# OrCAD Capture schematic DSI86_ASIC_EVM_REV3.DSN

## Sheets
1 PAGE05 AMBIENT LIGHT: size A; title: AMBIENT LIGHT SENSOR; rev: A.0; company: Texas Instruments, CIS/ICP; note: DSI86_ASIC_EVM_REV1
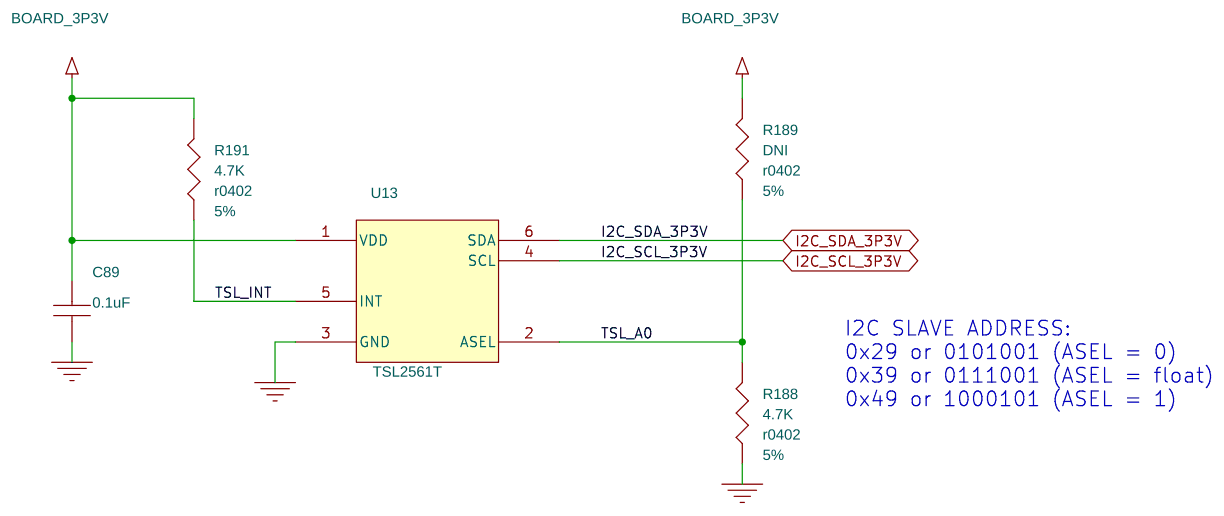
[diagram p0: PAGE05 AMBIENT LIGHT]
2 PAGE01 Title Page: title: SN65DSI86/96 EVM BLOCK DIAGRAM
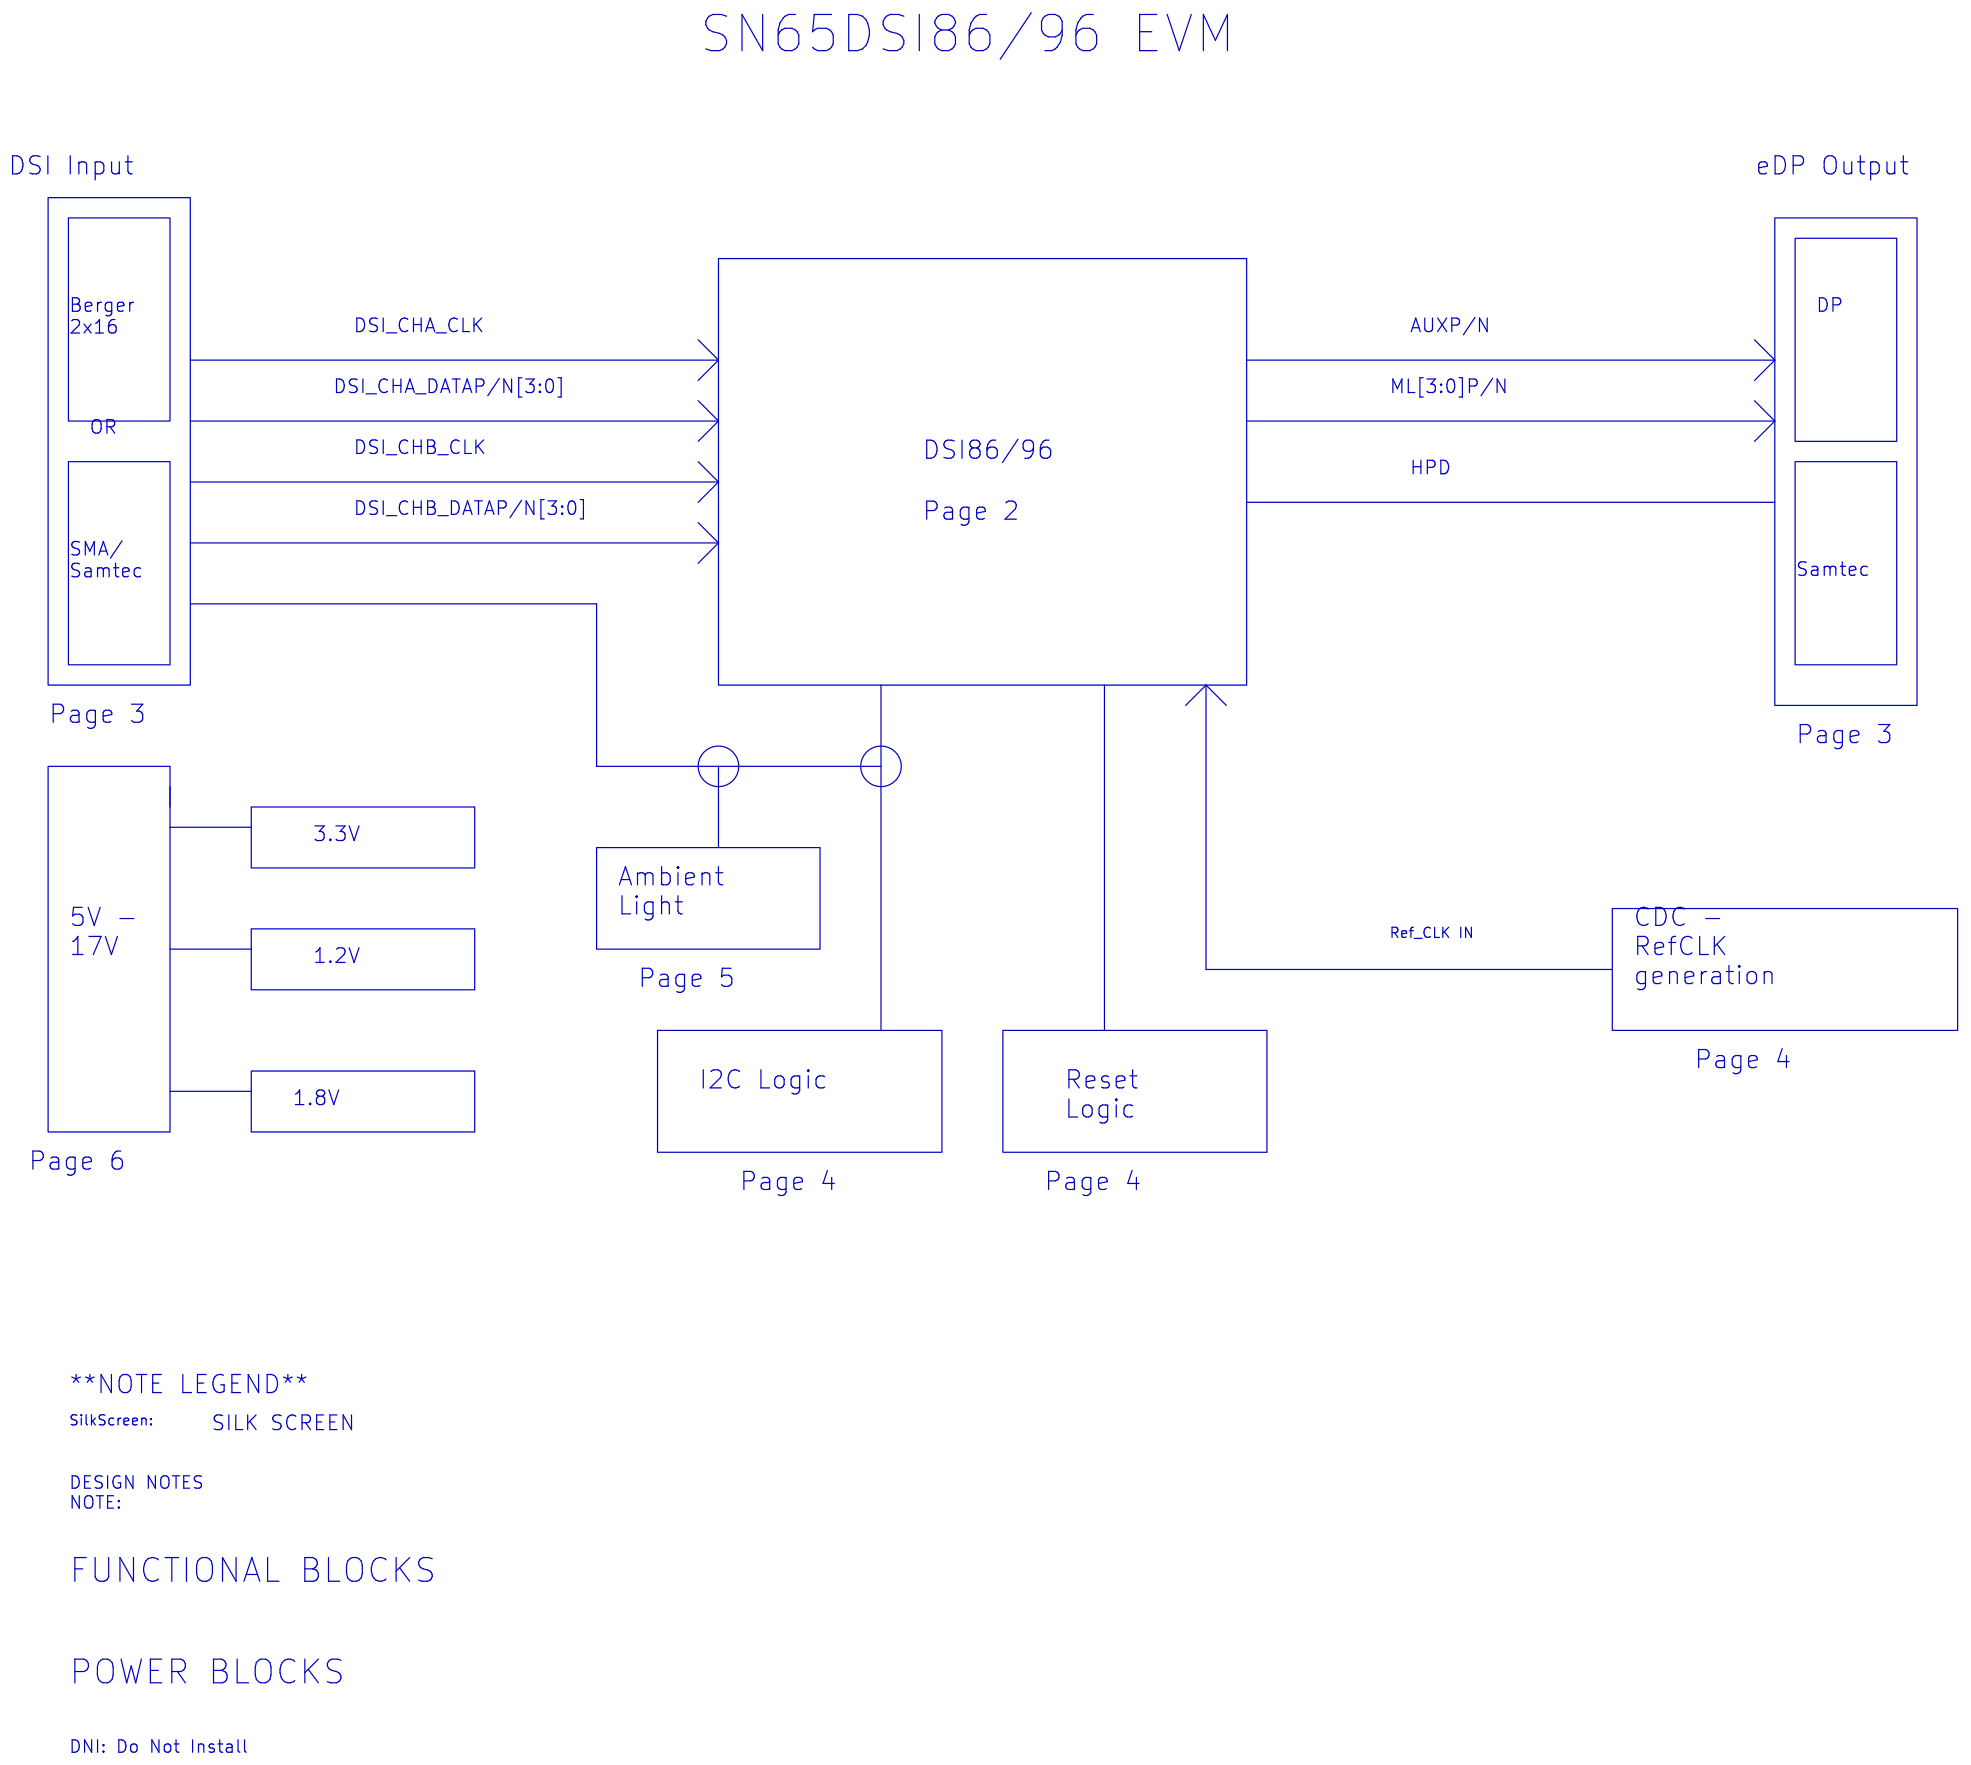
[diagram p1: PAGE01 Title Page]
3 PAGE02 DSI86: size C; title: SN65DSI86/96
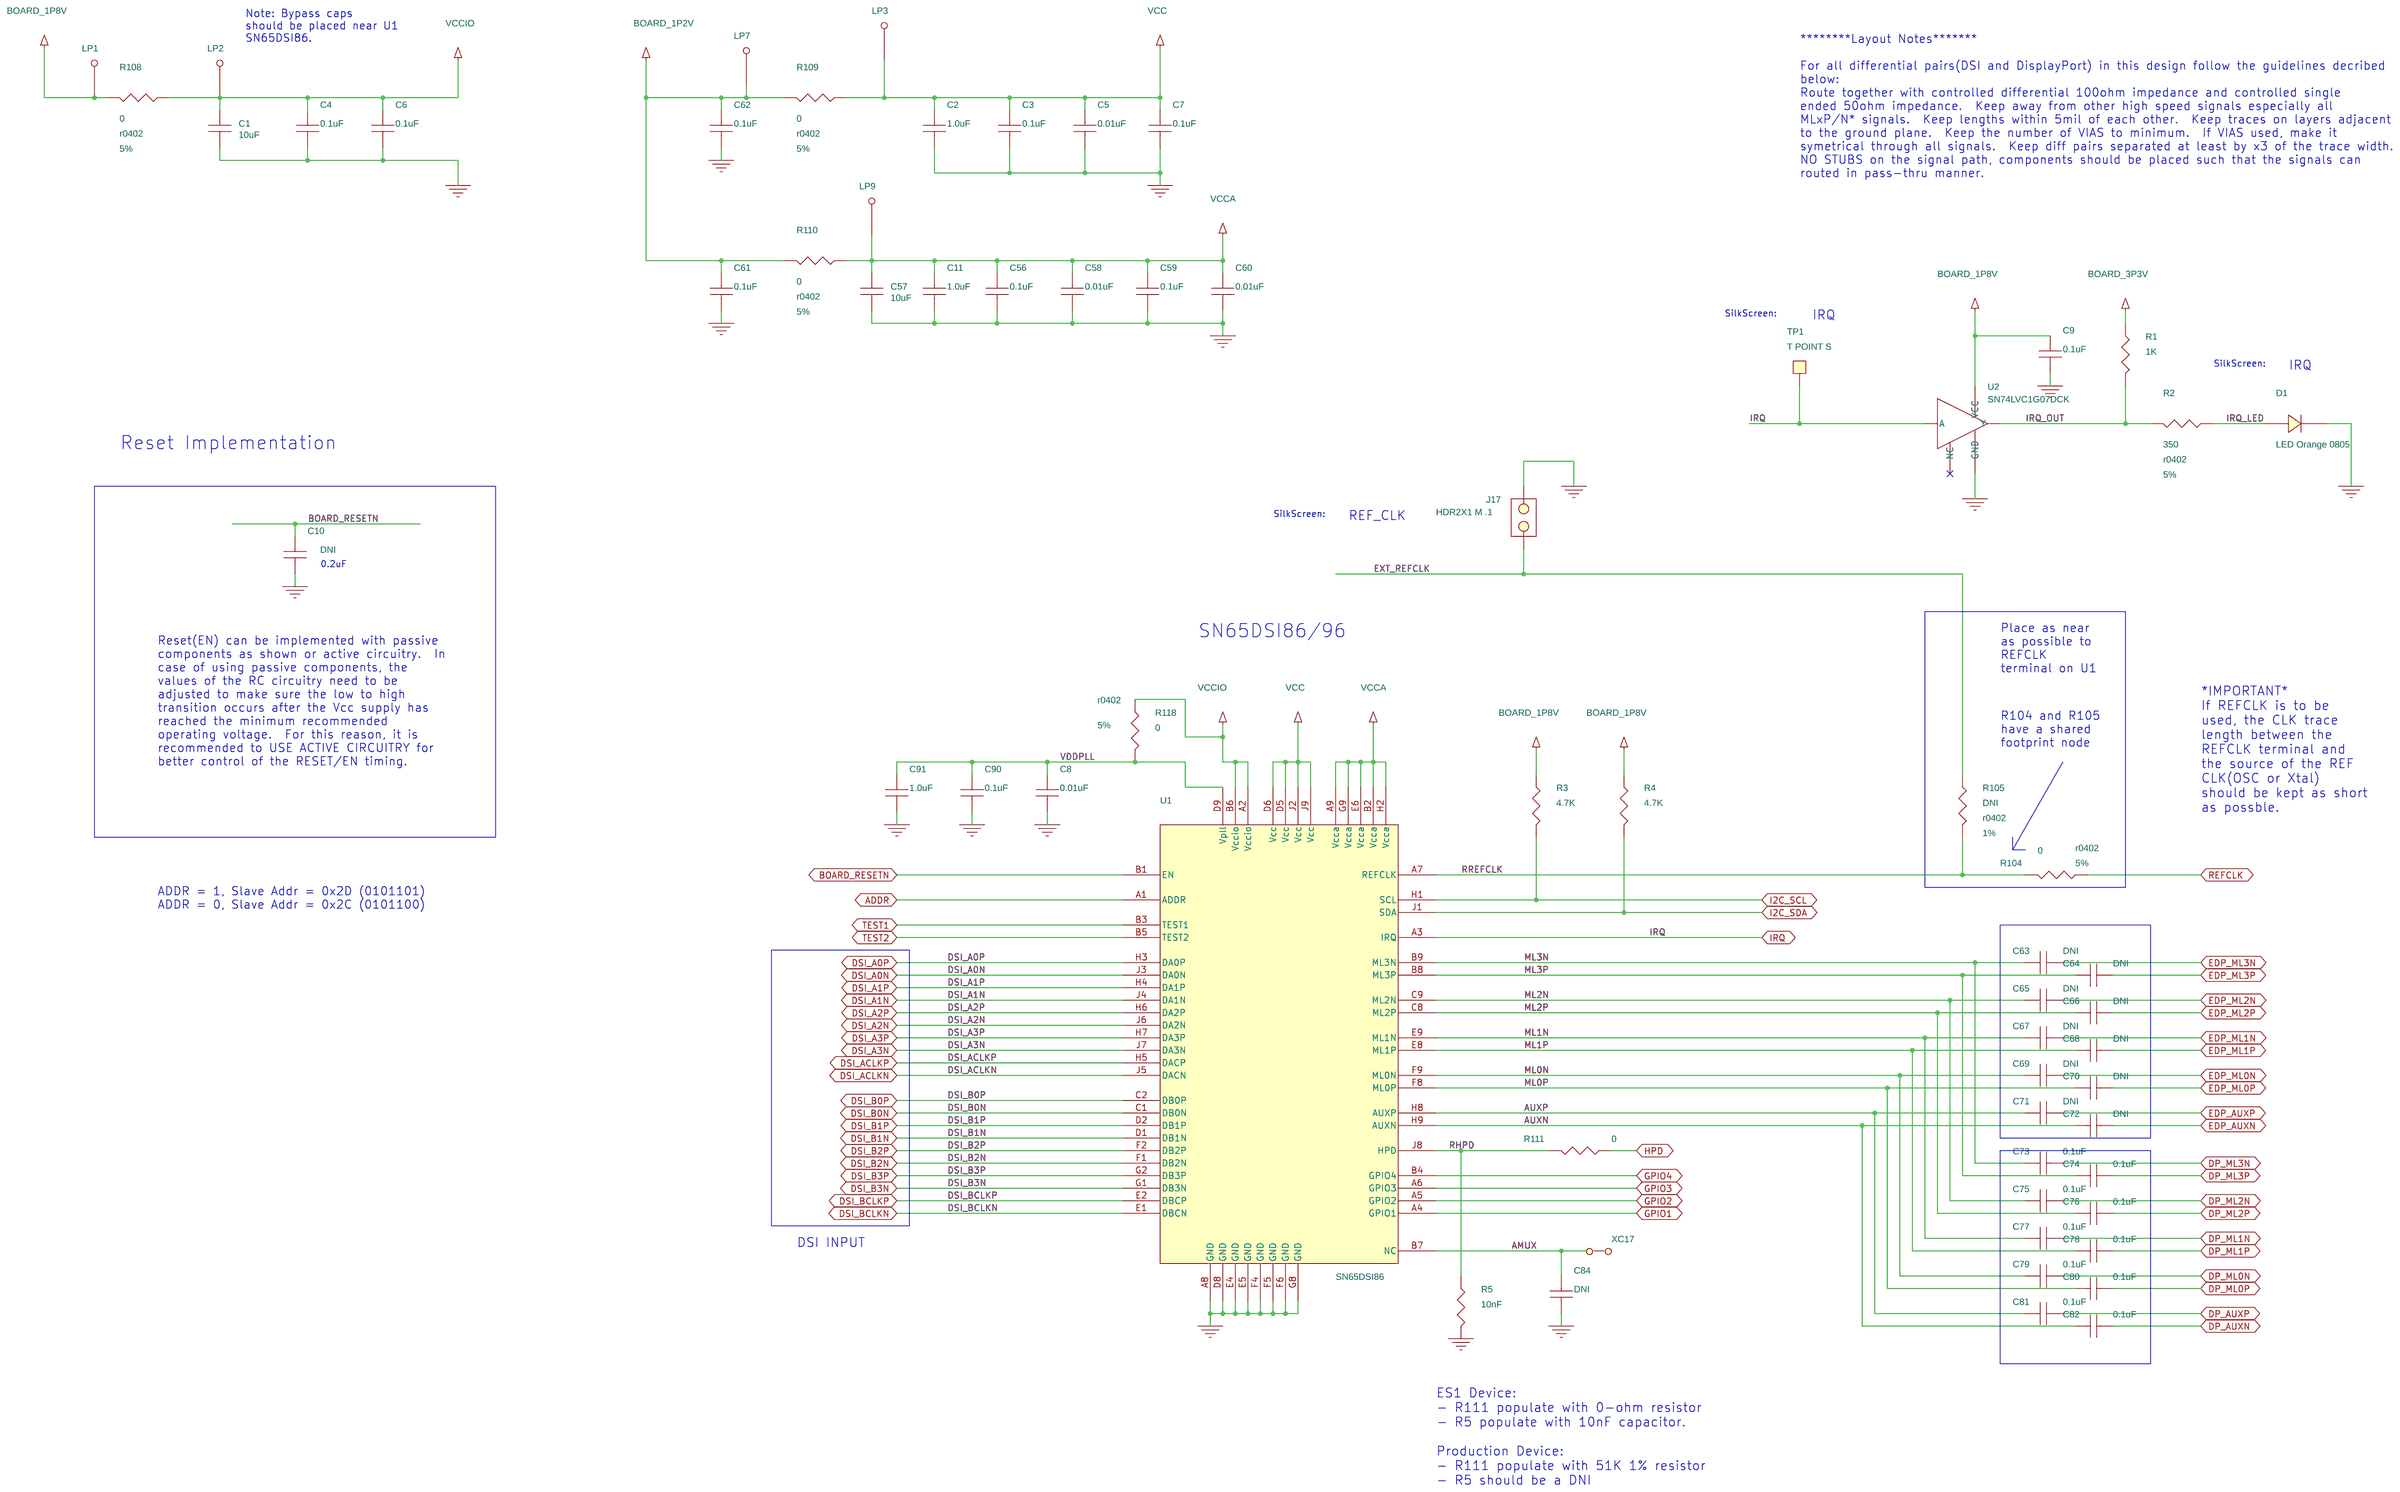
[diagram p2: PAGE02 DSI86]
4 PAGE03 Connectors: size D; title: CONNECTORS
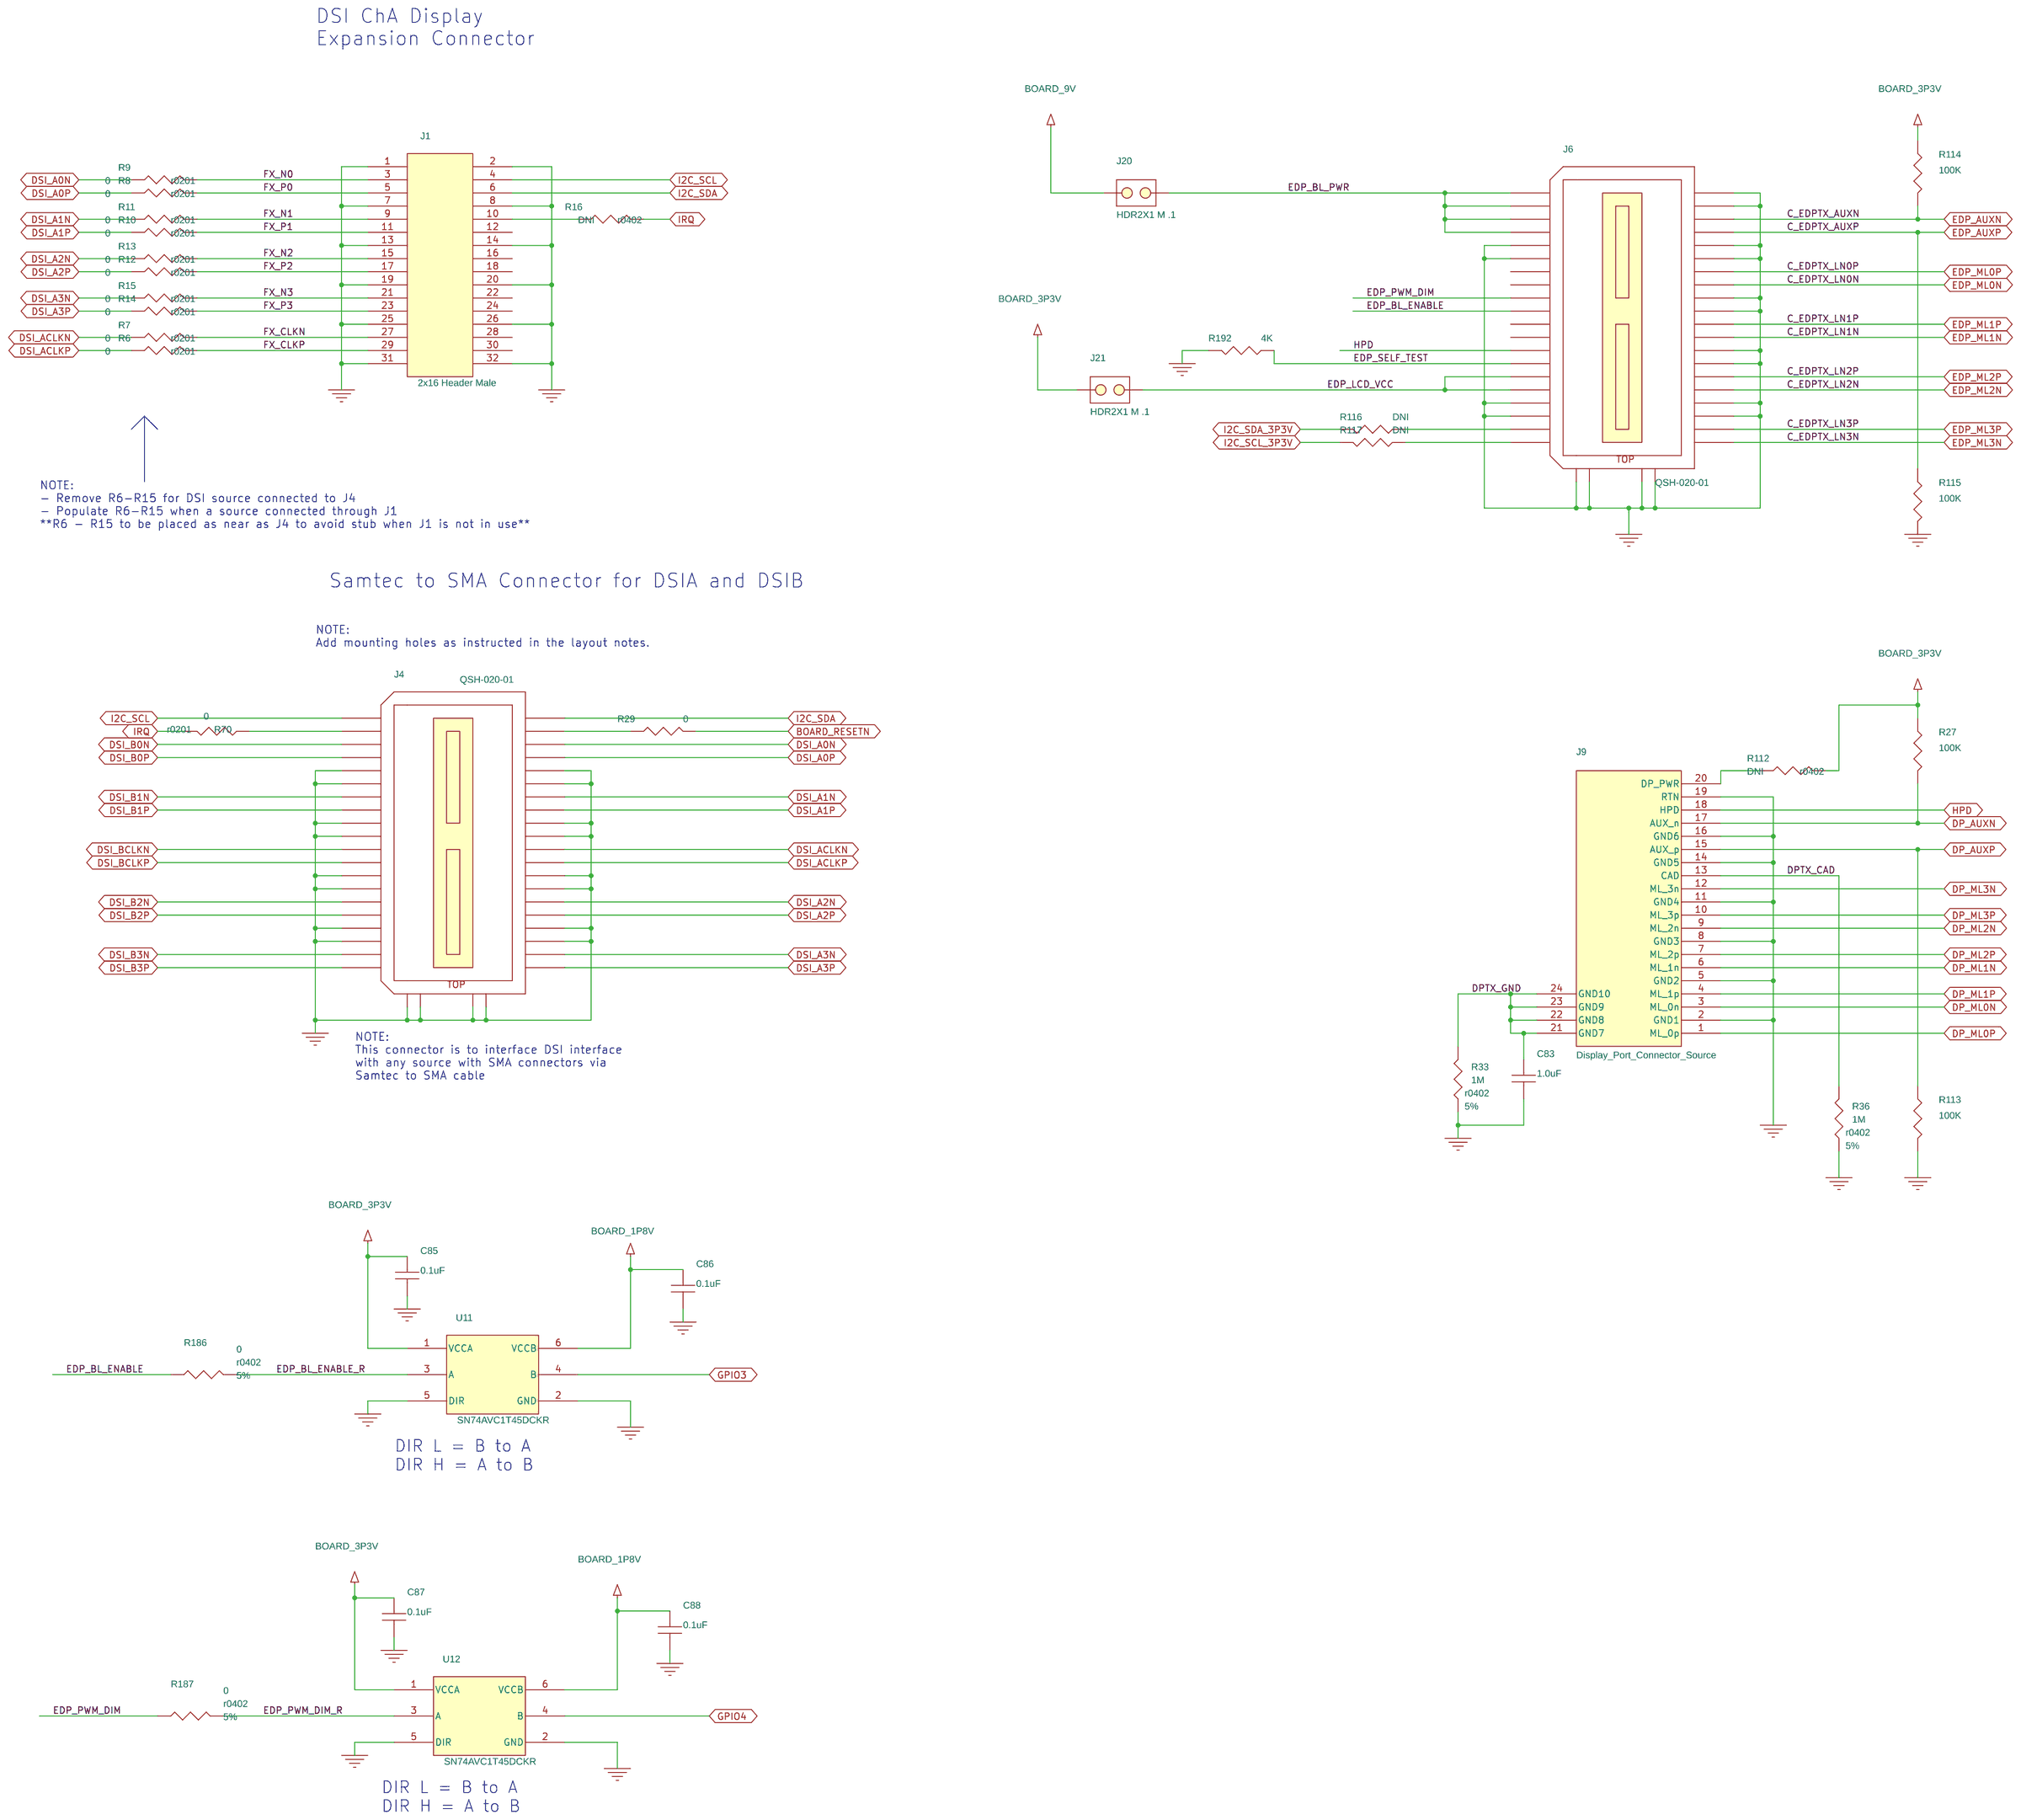
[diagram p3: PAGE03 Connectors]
5 PAGE04 Reset_CDC: size C; title: RESET AND CDC
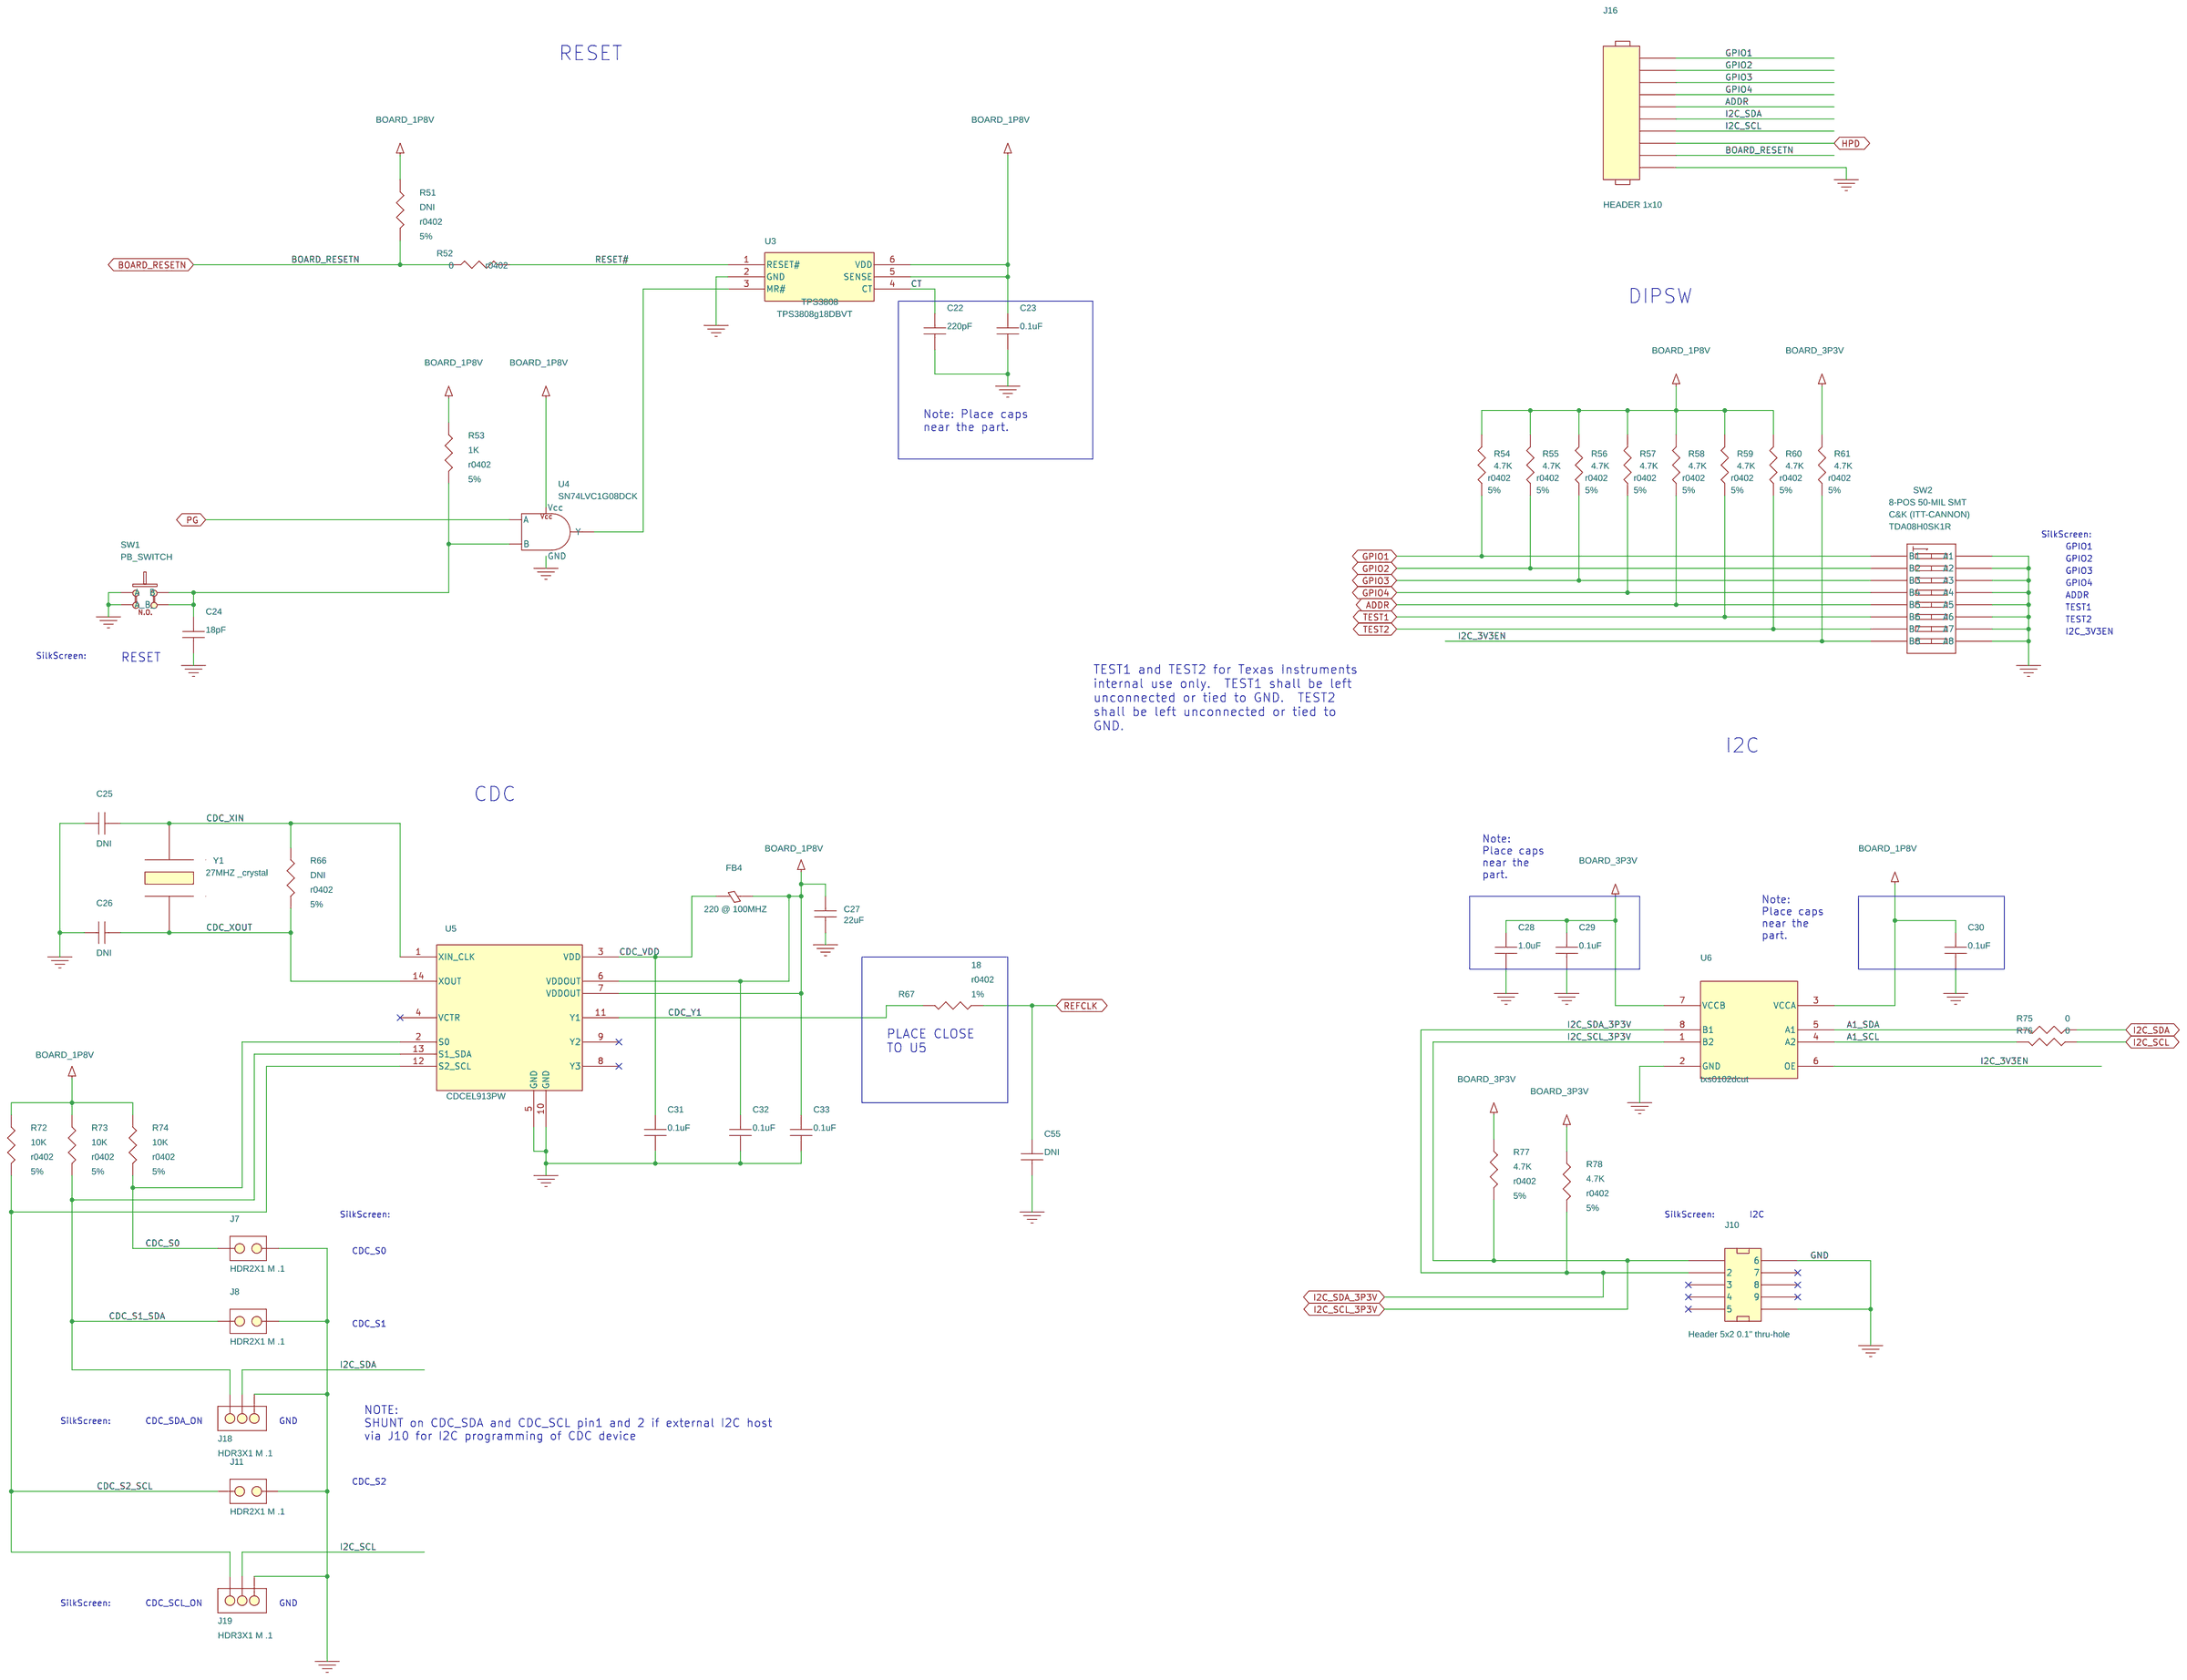
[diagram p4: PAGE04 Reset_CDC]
6 PAGE06 Power: size C; title: POWER
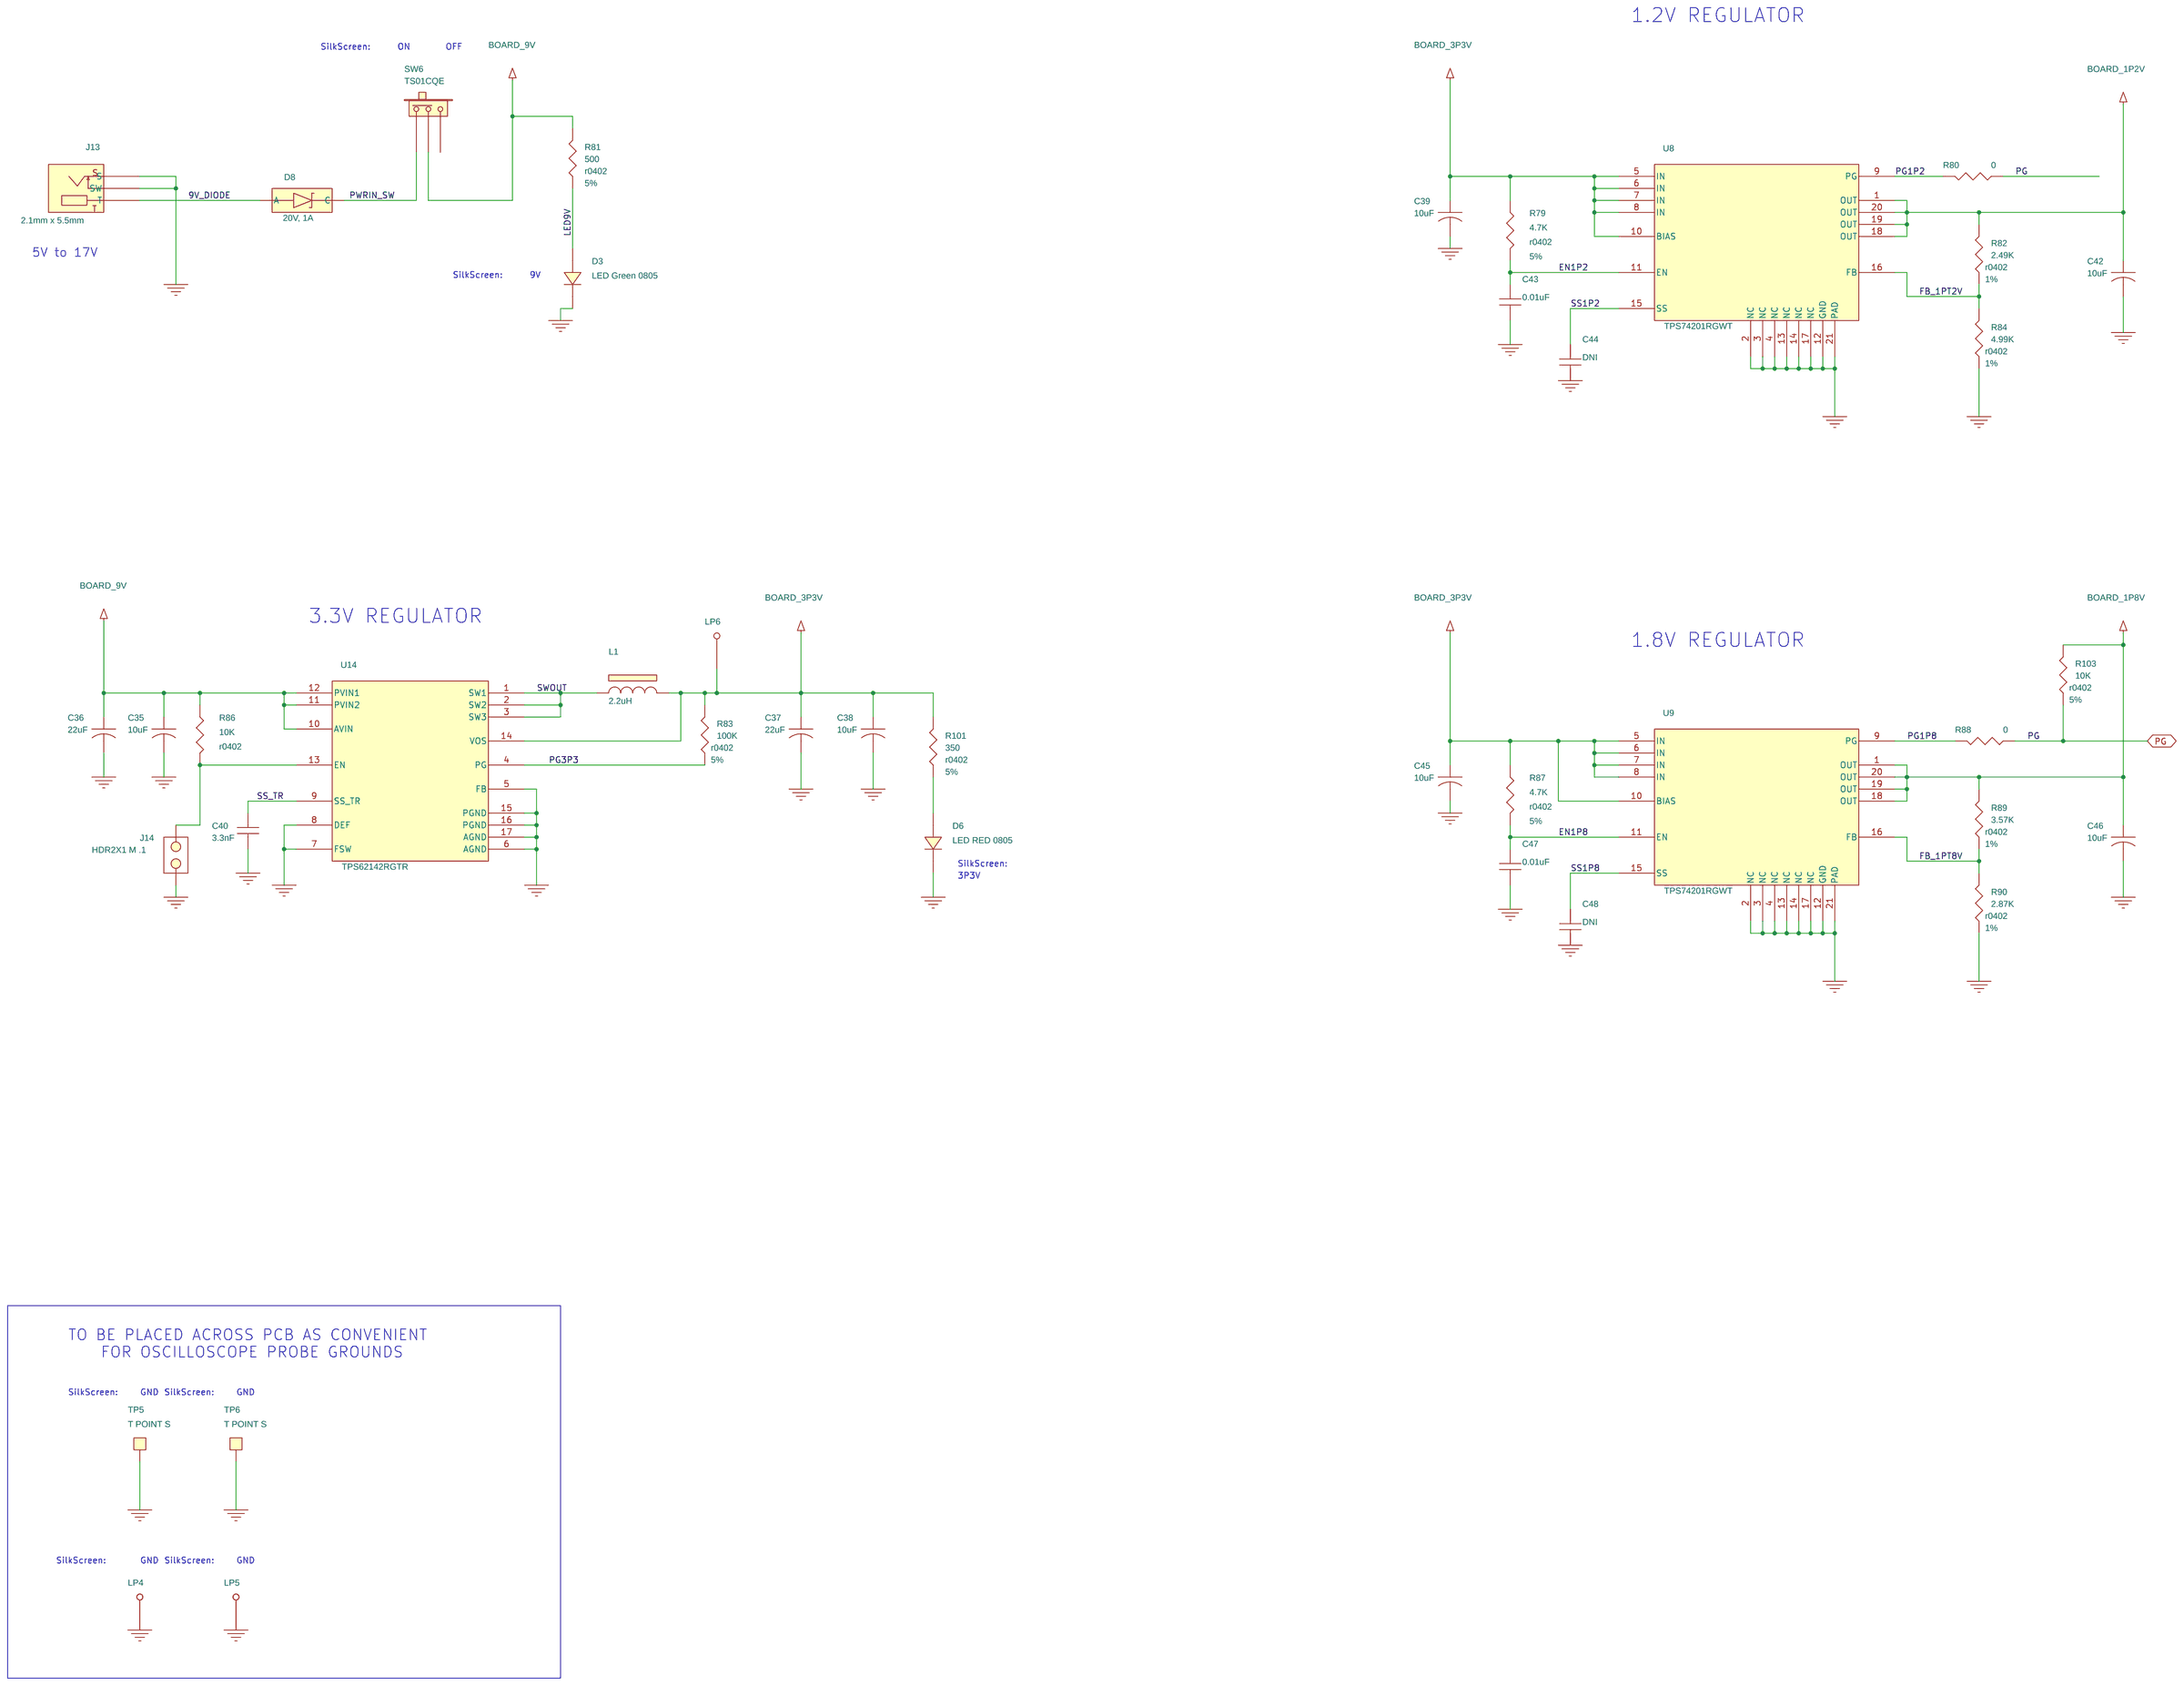
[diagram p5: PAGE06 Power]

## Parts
sheet PAGE02 DSI86
C1  10uF  [cc0805]
C2  1.0uF  [cc0402]
C3  0.1uF  [cc0201]
C4  0.1uF  [cc0201]
C5  0.01uF  [cc0201]
C6  0.1uF  [cc0201]
C7  0.1uF  [cc0201]
C8  0.01uF  [cc0201]
C9  0.1uF  [cc0201]
C10  DNI  [cc0201]
C11  1.0uF  [cc0402]
C56  0.1uF  [cc0201]
C57  10uF  [cc0805]
C58  0.01uF  [cc0201]
C59  0.1uF  [cc0201]
C60  0.01uF  [cc0201]
C61  0.1uF  [cc0201]
C62  0.1uF  [cc0201]
C63  DNI  [cc0201]
C64  DNI  [cc0201]
C65  DNI  [cc0201]
C66  DNI  [cc0201]
C67  DNI  [cc0201]
C68  DNI  [cc0201]
C69  DNI  [cc0201]
C70  DNI  [cc0201]
C71  DNI  [cc0201]
C72  DNI  [cc0201]
C73  0.1uF  [cc0201]
C74  0.1uF  [cc0201]
C75  0.1uF  [cc0201]
C76  0.1uF  [cc0201]
C77  0.1uF  [cc0201]
C78  0.1uF  [cc0201]
C79  0.1uF  [cc0201]
C80  0.1uF  [cc0201]
C81  0.1uF  [cc0201]
C82  0.1uF  [cc0201]
C84  DNI  [cc0201]
C90  0.1uF  [cc0201]
C91  1.0uF  [cc0402]
D1  LED Orange 0805  [cc0805]
J17  HDR2X1 M .1  [berg1x2]
LP1  LP  [TESTLOOP]
LP2  LP  [TESTLOOP]
LP3  LP  [TESTLOOP]
LP7  LP  [TESTLOOP]
LP9  LP  [TESTLOOP]
R1  1K  [r0402]
R2  350  [r0402]
R3  4.7K  [r0402]
R4  4.7K  [r0402]
R5  10nF  [r0402]
R104  0  [r0402]
R105  DNI  [r0402]
R108  0  [r0402]
R109  0  [r0402]
R110  0  [r0402]
R111  0  [r0402]
R118  0  [r0402]
TP1  T POINT S  [berg1x1]
U1  SN65DSI86  [Ironwood_81pin_7048]
U2  SN74LVC1G07DCK  [DCK5]
XC17  XC  [jmp_2p]
sheet PAGE03 Connectors
C83  1.0uF  [cc0402]
C85  0.1uF  [cc0402]
C86  0.1uF  [cc0402]
C87  0.1uF  [cc0402]
C88  0.1uF  [cc0402]
J1  2x16 Header Male  [berg2x16]
J4  QSH-020-01  [QSH-020_x]
J6  QSH-020-01  [QSH-020_x]
J9  Display_Port_Connector_Source  [DISPLAYPORT]
J20  HDR2X1 M .1  [berg1x2]
J21  HDR2X1 M .1  [berg1x2]
R6  0  [r0201]
R7  0  [r0201]
R8  0  [r0201]
R9  0  [r0201]
R10  0  [r0201]
R11  0  [r0201]
R12  0  [r0201]
R13  0  [r0201]
R14  0  [r0201]
R15  0  [r0201]
R16  DNI  [r0402]
R27  100K  [r0402]
R29  0  [r0402]
R33  1M  [r0402]
R36  1M  [r0402]
R70  0  [r0201]
R112  DNI  [r0402]
R113  100K  [r0402]
R114  100K  [r0402]
R115  100K  [r0402]
R116  DNI  [r0402]
R117  DNI  [r0402]
R186  0  [r0402]
R187  0  [r0402]
R192  4K  [r0402]
U11  SN74AVC1T45DCKR  [DCK6]
U12  SN74AVC1T45DCKR  [DCK6]
sheet PAGE04 Reset_CDC
C22  220pF  [cc0402]
C23  0.1uF  [cc0402]
C24  18pF  [cc0402]
C25  DNI  [cc0402]
C26  DNI  [cc0402]
C27  22uF  [cc0805]
C28  1.0uF  [cc0402]
C29  0.1uF  [cc0402]
C30  0.1uF  [cc0402]
C31  0.1uF  [cc0402]
C32  0.1uF  [cc0402]
C33  0.1uF  [cc0402]
C55  DNI  [cc0402]
FB4  220 @ 100MHZ  [r0603]
J7  HDR2X1 M .1  [HDR_2x1]
J8  HDR2X1 M .1  [HDR_2x1]
J10  Header 5x2 0.1" thru-hole  [berg2x5]
J11  HDR2X1 M .1  [HDR_2x1]
J16  HEADER 1x10  [berg1x10]
J18  HDR3X1 M .1  [berg1x3]
J19  HDR3X1 M .1  [berg1x3]
R51  DNI  [r0402]
R52  0  [r0402]
R53  1K  [r0402]
R54  4.7K  [r0402]
R55  4.7K  [r0402]
R56  4.7K  [r0402]
R57  4.7K  [r0402]
R58  4.7K  [r0402]
R59  4.7K  [r0402]
R60  4.7K  [r0402]
R61  4.7K  [r0402]
R66  DNI  [r0402]
R67  18  [r0402]
R72  10K  [r0402]
R73  10K  [r0402]
R74  10K  [r0402]
R75  0  [r0402]
R76  0  [r0402]
R77  4.7K  [r0402]
R78  4.7K  [r0402]
SW1  PB_SWITCH  [SW_MOM_2NO]
SW2  8-POS 50-MIL SMT  [TDA08H0SK1]
U3  TPS3808  [dbv_r-pdso-g6]
U4  SN74LVC1G08DCK  [DCK5]
U5  CDCEL913PW  [PW14]
U6  txs0102dcut  [DCU8]
Y1  27MHZ _crystal  [ABM8]
sheet PAGE05 AMBIENT LIGHT
C89  0.1uF  [cc0201]
R188  4.7K  [r0402]
R189  DNI  [r0402]
R191  4.7K  [r0402]
U13  TSL2561T  [TMB6]
sheet PAGE06 Power
C35  10uF  [cc0805]
C36  22uF  [cc1206]
C37  22uF  [cc0805]
C38  10uF  [cc0805]
C39  10uF  [cc0805]
C40  3.3nF  [cc0402]
C42  10uF  [cc0805]
C43  0.01uF  [cc0402]
C44  DNI  [cc0402]
C45  10uF  [cc0805]
C46  10uF  [cc0805]
C47  0.01uF  [cc0402]
C48  DNI  [cc0402]
D3  LED Green 0805  [r0805]
D6  LED RED 0805  [r0805]
D8  20V, 1A  [DO214AC]
J13  2.1mm x 5.5mm  [PJ-202AH]
J14  HDR2X1 M .1  [berg1x2]
L1  2.2uH  [4p5x4mm]
LP4  LP  [TESTLOOP]
LP5  LP  [TESTLOOP]
LP6  LP  [TESTLOOP]
R79  4.7K  [r0402]
R80  0  [r0402]
R81  500  [r0402]
R82  2.49K  [r0402]
R83  100K  [r0402]
R84  4.99K  [r0402]
R86  10K  [r0402]
R87  4.7K  [r0402]
R88  0  [r0402]
R89  3.57K  [r0402]
R90  2.87K  [r0402]
R101  350  [r0402]
R103  10K  [r0402]
SW6  TS01CQE  [TS01CQE]
TP5  T POINT S  [berg1x1]
TP6  T POINT S  [berg1x1]
U8  TPS74201RGWT  [RGW20]
U9  TPS74201RGWT  [RGW20]
U14  TPS62142RGTR  [RGT16]

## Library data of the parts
C1-C11 C22-C33 C43 C44 C47 C48 C55-C91 = CAP_NP
D1 = DIODE: Manuf: Rohm; Manuf PN: SML-211DTT86
J14 J17 J20 J21 = HDR2X1_M_.1
LP1-LP7 LP9 = TESTLOOP: Manuf: KOBIKONN; Manuf PN: 151-103-RC
R1-R16 R27 R29 R51-R61 R66 R70 R72-R81 R83 R86-R88 R101 R103 R104 R108-R118 R188 R189 R191 R192 = R_4: Tolerance: 5%
R67 R82 R84 R89 R90 R105 = R_4: Tolerance: 1%
TP1 TP5 TP6 = T_POINT_S
U1 = SN65DSI86
U2 = SN74LVC1G07_0: Manuf: TI
XC17 = XCON_0
J1 = 2x16_Header_Male: Digikey: S2011E-16-ND; Manuf PN: PBC16DAAN
J4 J6 = QSH-020-01_3
J9 = Display_Port_Connector_Source_0: Manuf: Molex; Manuf PN: 47272-0001
R33 R36 R186 R187 = R: Tolerance: 5%
U11 U12 = SN74AVC1T45DCKR
FB4 = FERRITE_BEAD: FBEAD 1000@100MHz; Device: BEAD1806; MFC: MuRata; Manuf: MuRata; Manuf PN: BLM18EG221SN1D; Part Number: BLM18EG221SN1D; Part#: BLM18EG221SN1D
J7 = HDR2X1_M_.1: Device: HDR2x1_100MIL; Manuf: AMP; Manuf PN: 103321-2; Manufacturer: AMP; Manufacturer Part Number: 103321-2; Manufacturer's Part Number: 103321-2; Part Number: 103321-2; TI_Silktext: S0
J8 = HDR2X1_M_.1: Device: HDR2x1_100MIL; Manuf: AMP; Manuf PN: 103321-2; Manufacturer: AMP; Manufacturer Part Number: 103321-2; Manufacturer's Part Number: 103321-2; Part Number: 103321-2; TI_Silktext: S1_SDA
J10 = CONN_PCB_5x2-S
J11 = HDR2X1_M_.1: Device: HDR2x1_100MIL; Manuf: AMP; Manuf PN: 103321-2; Manufacturer: AMP; Manufacturer Part Number: 103321-2; Manufacturer's Part Number: 103321-2; Part Number: 103321-2; TI_Silktext: S2_SCL
J16 = HEADER_10
J18 J19 = HDR3X1_M_.1
SW1 = PB_SWITCH_0: Manuf: OMRON; Manuf PN: B3SN-3012P; PART_NUMBER: BRD_RESETN; Part#: B3SN-3012P; TI_Silktext: BRD_RESETN
SW2 = SW_DIP-8_SM_0: Manuf: C&K(ITT-CANNON); Manuf PN: TDA08H0SK1R; Vendor: C&K (ITT-CANNON); Vendor Part Number: TDA08H0SK1R
U3 = TPS3808: Low Quiescent Current Supervisior Circuit (SOT23- 6Pin); Manuf: TI; Manuf PN: TPS3808g18DBVT; Manufacturer: Texas Instruments; Manufacturer's Part#: TPS3808g18DBVT; Part#: eprt-pcom-00033-0000; Status: OK
U4 = SN74AHC1G08DCK_2: Manuf: TI
U5 = CDCEL913PW
U6 = txs0102dcut_2: Manuf: TI
Y1 = 27MHZ__crystal
U13 = TSL2561T: Manuf: TAOS
C35 = CAP_0: CAP CER 10UF 6.3V 10% X5R 0805; Manuf: Murata; Manuf PN: GRM21BR61E106KA73L; TN: 207-0208-000; Voltage: 25V
C36 = CAP_0: CAP CER 10UF 6.3V 10% X5R 0805; Manuf: Murata; Manuf PN: GRM31CR61E226KE15L; TN: 207-0208-000; Voltage: 25V
C37 = CAP_0: CAP CER 10UF 6.3V 10% X5R 0805; TN: 207-0208-000
C38 C39 C42 C45 C46 = CAP_0: CAP CER 10UF 6.3V 10% X5R 0805; Mfr: MURATA; PN: GRM21BR60J106KE19L; TN: 207-0208-000
C40 = cc0402
D3 = DIODE: Manuf: Arrow (Lumex); Manuf PN: 670-1006 (SML_LX0805GC); PART_NUMBER: PWR_5V; TI_Silktext: PWR_5V
D6 = DIODE: Manuf: Rohm; Manuf PN: SML-211UT
D8 = BAT60A: MANUF P/N: CDBA120SL-G; Manuf: Comchip; Manuf PN: CDBA120SL-G
J13 = BNC_2: MANUF: CUI STACK; PART_NUMBER: 5V_SUPPLY; TI_Silktext: 5V_SUPPLY
L1 = INDUCTOR_FERRITE: Manuf: Vishay; Manuf PN: IHLP1616ABER2R2M11
SW6 = SW_SLIDE_SPDT2: Manuf: C&K Div.; Manufacturer: C&K Div.; Part_Type: Switch\Slide
U8 U9 = TPS74401RGWT_0
U14 = TPS62142RGTR

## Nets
9V_DIODE: D8.2(A) J13.1(T)
GND: C1.2 C2.2 C3.2 C4.2 C5.2 C6.2 C7.2 C8.2 C9.2 C10.2 C11.2 C22.2 C23.2 C24.2 C25.1 C26.1 C27.2 C28.2 C29.2 C30.2 C31.2 C32.2 C33.2 C35.2 C36.2 C37.2 C38.2 C39.2 C40.2 C42.2 C43.2 C44.2 C45.2 C46.2 C47.2 C48.2 C55.2 C56.2 C57.2 C58.2 C59.2 C60.2 C61.2 C62.2 C83.2 C84.2 C85.2 C86.2 C87.2 C88.2 C89.2 C90.2 C91.2 D1.2(K) D3.2(K) D6.2(K) J1.1 J1.2 J1.7 J1.8 J1.13 J1.14 J1.19 J1.20 J1.25 J1.26 J1.31 J1.32 J4.5 J4.6 J4.7 J4.8 J4.13 J4.14 J4.15 J4.16 J4.21 J4.22 J4.23 J4.24 J4.29 J4.30 J4.31 J4.32 J4.G1 J4.G2 J4.G3 J4.G4 J6.5 J6.6 J6.7 J6.8 J6.13 J6.15 J6.21 J6.23 J6.29 J6.30 J6.31 J6.32 J6.37 J6.39 J6.G1 J6.G2 J6.G3 J6.G4 J7.2 J8.2 J9.2(GND1) J9.5(GND2) J9.8(GND3) J9.11(GND4) J9.14(GND5) J9.16(GND6) J9.19(RTN) J10.2(6) J10.10 J11.2 J13.2(S) J13.3(SW) J14.1 J16.10 J17.2 J18.3 J19.3 LP4.1 LP5.1 R5.2 R33.1 R36.1 R84.1 R90.1 R113.2 R115.2 R188.1 R192.2 SW1.1(A) SW1.2(A_) SW2.1(A1) SW2.2(A2) SW2.3(A3) SW2.4(A4) SW2.5(A5) SW2.6(A6) SW2.7(A7) SW2.8(A8) TP5.1(TP) TP6.1(TP) U1.A8(GND) U1.D8(GND) U1.E4(GND) U1.E5(GND) U1.F4(GND) U1.F5(GND) U1.F6(GND) U1.G8(GND) U2.3(GND) U3.2(GND) U4.3(GND) U5.5(GND) U5.10(GND) U6.2(GND) U8.2(NC) U8.3(NC) U8.4(NC) U8.12(GND) U8.13(NC) U8.14(NC) U8.17(NC) U8.21(PAD) U9.2(NC) U9.3(NC) U9.4(NC) U9.12(GND) U9.13(NC) U9.14(NC) U9.17(NC) U9.21(PAD) U11.2(GND) U11.5(DIR) U12.2(GND) U12.5(DIR) U13.3(GND) U14.5(FB) U14.6(AGND) U14.7(FSW) U14.8(DEF) U14.15(PGND) U14.16(PGND) U14.17(AGND) Y1.2(GND) Y1.4(GND)
VCC: C2.1 C3.1 C5.1 C7.1 LP3.1 R109.1 U1.D5(Vcc) U1.D6(Vcc) U1.J2(Vcc) U1.J9(Vcc)
VCCA: C11.1 C56.1 C57.1 C58.1 C59.1 C60.1 LP9.1 R110.1 U1.A9(Vcca) U1.B2(Vcca) U1.E6(Vcca) U1.G9(Vcca) U1.H2(Vcca)
VCCIO: C1.1 C4.1 C6.1 LP2.1 R108.1 R118.1 U1.A2(Vccio) U1.B6(Vccio)
VDDPLL: C8.1 C90.1 C91.1 R118.2 U1.D9(Vpll)
A1_SCL: R76.2 U6.4(A2)
A1_SDA: R75.2 U6.5(A1)
ADDR: J16.5 R58.1 SW2.12(B5) U1.A1(ADDR)
AMUX: C84.1 U1.B7(NC) XC17.1
AUXN: C72.1 C82.1 U1.H9(AUXN)
AUXP: C71.1 C81.1 U1.H8(AUXP)
BOARD_1P2V: C42.1 C61.1 C62.1 LP7.1 R82.2 R109.2 R110.2 U8.1(OUT) U8.18(OUT) U8.19(OUT) U8.20(OUT)
BOARD_1P8V: C9.1 C23.1 C27.1 C30.1 C32.1 C33.1 C46.1 C86.1 C88.1 FB4.2 LP1.1 R3.1 R4.1 R51.1 R53.1 R54.2 R55.2 R56.2 R57.2 R58.2 R59.2 R60.2 R72.1 R73.1 R74.1 R89.2 R103.2 R108.2 U2.5(VCC) U3.5(SENSE) U3.6(VDD) U4.5(Vcc) U5.6(VDDOUT) U5.7(VDDOUT) U6.3(VCCA) U9.1(OUT) U9.18(OUT) U9.19(OUT) U9.20(OUT) U11.6(VCCB) U12.6(VCCB)
BOARD_3P3V: C28.1 C29.1 C37.1 C38.1 C39.1 C45.1 C85.1 C87.1 C89.1 J21.2 L1.2 LP6.1 R1.1 R27.1 R61.2 R77.1 R78.1 R79.1 R83.2 R87.1 R101.2 R112.2 R114.1 R189.2 R191.2 U6.7(VCCB) U8.5(IN) U8.6(IN) U8.7(IN) U8.8(IN) U8.10(BIAS) U9.5(IN) U9.6(IN) U9.7(IN) U9.8(IN) U9.10(BIAS) U11.1(VCCA) U12.1(VCCA) U13.1(VDD) U14.14(VOS)
BOARD_9V: C35.1 C36.1 J20.2 R81.2 R86.1 SW6.2 U14.10(AVIN) U14.11(PVIN2) U14.12(PVIN1)
BOARD_RESETN: C10.1 J16.9 R29.2 R51.2 R52.1 U1.B1(EN)
CDC_S0: J7.1 R74.2 U5.2(S0)
CDC_S1_SDA: J8.1 J18.1 R73.2 U5.13(S1_SDA)
CDC_S2_SCL: J11.1 J19.1 R72.2 U5.12(S2_SCL)
CDC_VDD: C31.1 FB4.1 U5.3(VDD)
CDC_XIN: C25.2 R66.1 U5.1(XIN_CLK) Y1.3(XO)
CDC_XOUT: C26.2 R66.2 U5.14(XOUT) Y1.1(XI)
CDC_Y1: R67.2 U5.11(Y1)
CT: C22.1 U3.4(CT)
DP_AUXN: C82.2 J9.17(AUX_n) R27.2
DP_AUXP: C81.2 J9.15(AUX_p) R113.1
DP_ML0N: C79.2 J9.3(ML_0n)
DP_ML0P: C80.2 J9.1(ML_0p)
DP_ML1N: C77.2 J9.6(ML_1n)
DP_ML1P: C78.2 J9.4(ML_1p)
DP_ML2N: C75.2 J9.9(ML_2n)
DP_ML2P: C76.2 J9.7(ML_2p)
DP_ML3N: C73.2 J9.12(ML_3n)
DP_ML3P: C74.2 J9.10(ML_3p)
DPTX_CAD: J9.13(CAD) R36.2
DPTX_GND: C83.1 J9.21(GND7) J9.22(GND8) J9.23(GND9) J9.24(GND10) R33.2
DSI_A0N: J4.35 R9.1 U1.J3(DA0N)
DSI_A0P: J4.33 R8.1 U1.H3(DA0P)
DSI_A1N: J4.27 R11.1 U1.J4(DA1N)
DSI_A1P: J4.25 R10.1 U1.H4(DA1P)
DSI_A2N: J4.11 R13.1 U1.J6(DA2N)
DSI_A2P: J4.9 R12.1 U1.H6(DA2P)
DSI_A3N: J4.3 R15.1 U1.J7(DA3N)
DSI_A3P: J4.1 R14.1 U1.H7(DA3P)
DSI_ACLKN: J4.19 R7.1 U1.J5(DACN)
DSI_ACLKP: J4.17 R6.1 U1.H5(DACP)
DSI_B0N: J4.36 U1.C1(DB0N)
DSI_B0P: J4.34 U1.C2(DB0P)
DSI_B1N: J4.28 U1.D1(DB1N)
DSI_B1P: J4.26 U1.D2(DB1P)
DSI_B2N: J4.12 U1.F1(DB2N)
DSI_B2P: J4.10 U1.F2(DB2P)
DSI_B3N: J4.4 U1.G1(DB3N)
DSI_B3P: J4.2 U1.G2(DB3P)
DSI_BCLKN: J4.20 U1.E1(DBCN)
DSI_BCLKP: J4.18 U1.E2(DBCP)
EDP_AUXN: C72.2 J6.35 R114.2
EDP_AUXP: C71.2 J6.33 R115.1
EDP_BL_ENABLE: J6.22 R186.1
EDP_BL_ENABLE_R: R186.2 U11.3(A)
EDP_BL_PWR: J6.34 J6.36 J6.38 J6.40 J20.1
EDP_LCD_VCC: J6.10 J6.12 J21.1
EDP_ML0N: C69.2 J6.25
EDP_ML0P: C70.2 J6.27
EDP_ML1N: C67.2 J6.17
EDP_ML1P: C68.2 J6.19
EDP_ML2N: C65.2 J6.9
EDP_ML2P: C66.2 J6.11
EDP_ML3N: C63.2 J6.1
EDP_ML3P: C64.2 J6.3
EDP_PWM_DIM: J6.24 R187.1
EDP_PWM_DIM_R: R187.2 U12.3(A)
EDP_SELF_TEST: J6.14 R192.1
EN1P2: C43.1 R79.2 U8.11(EN)
EN1P8: C47.1 R87.2 U9.11(EN)
EXT_REFCLK: J17.1 R105.1
FB_1PT2V: R82.1 R84.2 U8.16(FB)
FB_1PT8V: R89.1 R90.2 U9.16(FB)
FX_CLKN: J1.27 R7.2
FX_CLKP: J1.29 R6.2
FX_N0: J1.3 R9.2
FX_N1: J1.9 R11.2
FX_N2: J1.15 R13.2
FX_N3: J1.21 R15.2
FX_P0: J1.5 R8.2
FX_P1: J1.11 R10.2
FX_P2: J1.17 R12.2
FX_P3: J1.23 R14.2
GPIO1: J16.1 R54.1 SW2.16(B1) U1.A4(GPIO1)
GPIO2: J16.2 R55.1 SW2.15(B2) U1.A5(GPIO2)
GPIO3: J16.3 R56.1 SW2.14(B3) U1.A6(GPIO3) U11.4(B)
GPIO4: J16.4 R57.1 SW2.13(B4) U1.B4(GPIO4) U12.4(B)
HPD: J6.16 J9.18(HPD) J16.8 R111.1
I2C_3V3EN: R61.1 SW2.9(B8) U6.6(OE)
I2C_SCL: J1.4 J4.40 J16.7 J19.2 R3.2 R76.1 U1.H1(SCL)
I2C_SCL_3P3V: J10.1 R77.2 R117.2 U6.1(B2) U13.4(SCL)
I2C_SDA: J1.6 J4.39 J16.6 J18.2 R4.2 R75.1 U1.J1(SDA)
I2C_SDA_3P3V: J10.3(2) R78.2 R116.2 U6.8(B1) U13.6(SDA)
IRQ: R16.2 R70.2 TP1.1(TP) U1.A3(IRQ) U2.2(A)
IRQ_LED: D1.1(A) R2.1
IRQ_OUT: R1.2 R2.2 U2.4(Y)
LED9V: D3.1(A) R81.1
ML0N: C69.1 C79.1 U1.F9(ML0N)
ML0P: C70.1 C80.1 U1.F8(ML0P)
ML1N: C67.1 C77.1 U1.E9(ML1N)
ML1P: C68.1 C78.1 U1.E8(ML1P)
ML2N: C65.1 C75.1 U1.C9(ML2N)
ML2P: C66.1 C76.1 U1.C8(ML2P)
ML3N: C63.1 C73.1 U1.B9(ML3N)
ML3P: C64.1 C74.1 U1.B8(ML3P)
PG: R80.1 R88.1 R103.1 U4.1(A)
PG1P2: R80.2 U8.9(PG)
PG1P8: R88.2 U9.9(PG)
PG3P3: R83.1 U14.4(PG)
PWRIN_SW: D8.1(C) SW6.1
REFCLK: C55.1 R67.1 R104.1
RESET#: R52.2 U3.1(RESET#)
RHPD: R5.1 R111.2 U1.J8(HPD)
RREFCLK: R104.2 R105.2 U1.A7(REFCLK)
SS1P2: C44.1 U8.15(SS)
SS1P8: C48.1 U9.15(SS)
SS_TR: C40.1 U14.9(SS_TR)
SWOUT: L1.1 U14.1(SW1) U14.2(SW2) U14.3(SW3)
TEST1: R59.1 SW2.11(B6) U1.B3(TEST1)
TEST2: R60.1 SW2.10(B7) U1.B5(TEST2)
TSL_A0: R188.2 R189.1 U13.2(ASEL)
TSL_INT: R191.1 U13.5(INT)
N16337340: U3.3(MR#) U4.4(Y)
N16337368: C24.1 R53.2 SW1.3(B_) SW1.4(B) U4.2(B)
N16553551: J4.38 R70.1
N16649721: J4.37 R29.1
N16727318: D6.1(A) R101.1
N16746732: J9.20(DP_PWR) R112.1
N16749444: J6.4 R116.1
N16749448: J6.2 R117.1
N16759353: J14.2 R86.2 U14.13(EN)
N16817438: J1.10 R16.1

Not connected (* = marked no-connect by the designer): J1 12 16 18 22 24 28 30; J6 18 20 26 28; J10 4(7)* 5(3)* 6(8)* 7(4)* 8(9)* 9(5)*; SW6 3; U2 1(NC)*; U5 4(VCTR)* 8(Y3)* 9(Y2)*; XC17 2

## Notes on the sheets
sheet 1
- I2C SLAVE ADDRESS:
  0x29 or 0101001 (ASEL = 0)
  0x39 or 0111001 (ASEL = float)
  0x49 or 1000101 (ASEL = 1)
sheet 2
- SN65DSI86/96 EVM
- DSI Input
- eDP Output
- Berger
  2x16
- DP
- DSI_CHA_CLK
- AUXP/N
- DSI_CHA_DATAP/N[3:0]
- ML[3:0]P/N
- OR
- DSI_CHB_CLK
- DSI86/96
- HPD
- DSI_CHB_DATAP/N[3:0]
- Page 2
- SMA/
  Samtec
- Samtec
- Page 3
- Page 3
- 3.3V
- Ambient
  Light
- 5V -
  17V
- CDC -
  RefCLK
  generation
- Ref_CLK IN
- 1.2V
- Page 5
- Page 4
- I2C Logic
- Reset
  Logic
- 1.8V
- Page 6
- Page 4
- Page 4
- **NOTE LEGEND**
- SilkScreen:
- SILK SCREEN
- DESIGN NOTES
  NOTE:
- FUNCTIONAL BLOCKS
- POWER BLOCKS
- DNI: Do Not Install
sheet 3
- Note: Bypass caps
  should be placed near U1
  SN65DSI86.
- ********Layout Notes*******
  For all differential pairs(DSI and DisplayPort) in this design follow the guidelines decribed
  below:
  Route together with controlled differential 100ohm impedance and controlled single
  ended 50ohm impedance.  Keep away from other high speed signals especially all
  MLxP/N* signals.  Keep lengths within 5mil of each other.  Keep traces on layers adjacent
  to the ground plane.  Keep the number of VIAS to minimum.  If VIAS used, make it
  symetrical through all signals.  Keep diff pairs separated at least by x3 of the trace width.
  NO STUBS on the signal path, components should be placed such that the signals can
  routed in pass-thru manner.
- SilkScreen:
- IRQ
- SilkScreen:
- IRQ
- Reset Implementation
- SilkScreen:
- REF_CLK
- 0.2uF
- SN65DSI86/96
- Place as near
  as possible to
  REFCLK
  terminal on U1
- Reset(EN) can be implemented with passive
  components as shown or active circuitry.  In
  case of using passive components, the
  values of the RC circuitry need to be
  adjusted to make sure the low to high
  transition occurs after the Vcc supply has
  reached the minimum recommended
  operating voltage.  For this reason, it is
  recommended to USE ACTIVE CIRCUITRY for
  better control of the RESET/EN timing.
- *IMPORTANT*
  If REFCLK is to be
  used, the CLK trace
  length between the
  REFCLK terminal and
  the source of the REF
  CLK(OSC or Xtal)
  should be kept as short
  as possble.
- R104 and R105
  have a shared
  footprint node
- ADDR = 1, Slave Addr = 0x2D (0101101)
  ADDR = 0, Slave Addr = 0x2C (0101100)
- DSI INPUT
- ES1 Device:
  - R111 populate with 0-ohm resistor
  - R5 populate with 10nF capacitor.
  Production Device:
  - R111 populate with 51K 1% resistor
  - R5 should be a DNI
sheet 4
- DSI ChA Display
  Expansion Connector
- NOTE:
  - Remove R6-R15 for DSI source connected to J4
  - Populate R6-R15 when a source connected through J1
  **R6 - R15 to be placed as near as J4 to avoid stub when J1 is not in use**
- Samtec to SMA Connector for DSIA and DSIB
- NOTE:
  Add mounting holes as instructed in the layout notes.
- NOTE:
  This connector is to interface DSI interface
  with any source with SMA connectors via
  Samtec to SMA cable
- DIR L = B to A
  DIR H = A to B
- DIR L = B to A
  DIR H = A to B
sheet 5
- RESET
- DIPSW
- Note: Place caps
  near the part.
- SilkScreen:
- GPIO1
- GPIO2
- GPIO3
- GPIO4
- ADDR
- TEST1
- TEST2
- I2C_3V3EN
- SilkScreen:
- RESET
- TEST1 and TEST2 for Texas Instruments
  internal use only.  TEST1 shall be left
  unconnected or tied to GND.  TEST2
  shall be left unconnected or tied to
  GND.
- I2C
- CDC
- Note:
  Place caps
  near the
  part.
- Note:
  Place caps
  near the
  part.
- PLACE CLOSE
  TO U5
- SilkScreen:
- SilkScreen:
- I2C
- CDC_S0
- CDC_S1
- NOTE:
  SHUNT on CDC_SDA and CDC_SCL pin1 and 2 if external I2C host
  via J10 for I2C programming of CDC device
- SilkScreen:
- CDC_SDA_ON
- GND
- CDC_S2
- SilkScreen:
- CDC_SCL_ON
- GND
sheet 6
- 1.2V REGULATOR
- SilkScreen:
- ON
- OFF
- 5V to 17V
- SilkScreen:
- 9V
- 3.3V REGULATOR
- 1.8V REGULATOR
- SilkScreen:
- 3P3V
- TO BE PLACED ACROSS PCB AS CONVENIENT
      FOR OSCILLOSCOPE PROBE GROUNDS
- SilkScreen:
- GND
- SilkScreen:
- GND
- SilkScreen:
- GND
- SilkScreen:
- GND
